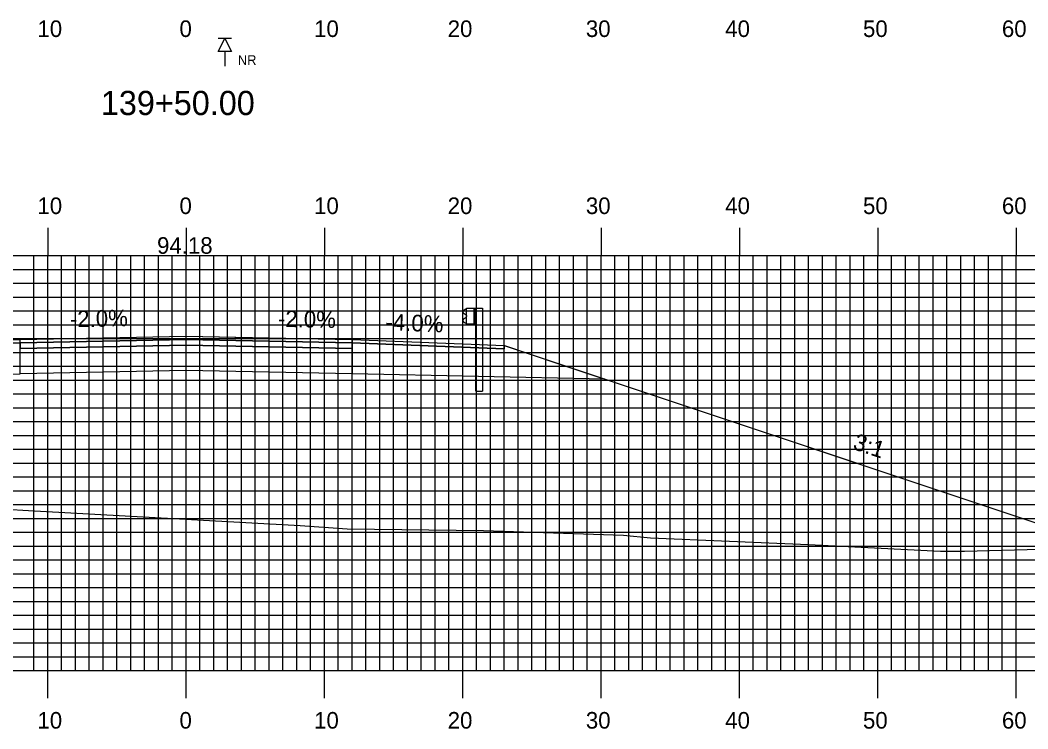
# Model space of a CAD drawing. Extents: x 1775957 to 1776301, y 442591 to 442811.
# Drawn here: x 1776111.2 to 1776184.1, y 442649.4 to 442700.7 of the extents above; entities that cross this region are included whole.
import ezdxf

# ---------------------------------------------------------------- set-up
doc = ezdxf.new("R2010")
doc.units = 0
for name, color, linetype in [('ANNOTATION', 7, 'Continuous'), ('BORING - NO REFUSAL', 7, 'Continuous'), ('D_Guardrail_Beam_Rt', 7, 'Continuous'), ('D_Roadway_Centerline', 7, 'Continuous'), ('D_Roadway_Centerline_Text', 7, 'Continuous'), ('D_Roadway_Edge_Shoulder', 7, 'Continuous'), ('D_Roadway_Edge_TW', 7, 'Continuous'), ('D_Roadway_Pavement', 7, 'Continuous'), ('D_Roadway_SlopeLines', 7, 'Continuous'), ('D_Roadway_SubGrade', 7, 'Continuous'), ('H_V ANNOTATION', 7, 'Continuous'), ('MAJOR', 7, 'Continuous'), ('MINOR', 7, 'Continuous'), ('S_Roadway_Centerline', 7, 'Continuous')]:
    doc.layers.add(name, color=color, linetype=linetype)

msp = doc.modelspace()

# ---------------------------------------------------------------- linework, layer by layer
at = {"layer": 'BORING - NO REFUSAL'}
for p, q in [((1776126.504, 442699.365), (1776125.545, 442699.365)), ((1776126.024, 442698.406), (1776126.024, 442697.347))]:
    msp.add_line(p, q, dxfattribs=at)
msp.add_lwpolyline([(1776126.024, 442699.365), (1776126.504, 442698.406), (1776125.545, 442698.406)], close=True, dxfattribs=at)
at = {"layer": 'D_Guardrail_Beam_Rt'}
for p, q in [((1776143.406, 442679.763), (1776143.262, 442679.663)), ((1776143.262, 442679.52), (1776143.458, 442679.384)), ((1776143.496, 442679.784), (1776143.422, 442679.77)), ((1776143.491, 442679.319), (1776143.491, 442679.249)), ((1776143.496, 442679.868), (1776144.183, 442679.868)), ((1776143.496, 442678.701), (1776143.496, 442679.868)), ((1776144.017, 442679.868), (1776144.017, 442678.701)), ((1776144.121, 442679.868), (1776144.121, 442678.701)), ((1776144.183, 442679.868), (1776144.654, 442679.868)), ((1776144.183, 442679.868), (1776144.183, 442678.701)), ((1776144.654, 442679.868), (1776144.654, 442673.868)), ((1776143.458, 442679.185), (1776143.262, 442679.049)), ((1776143.262, 442678.905), (1776143.406, 442678.805)), ((1776143.422, 442678.799), (1776143.496, 442678.784)), ((1776144.183, 442678.701), (1776143.496, 442678.701)), ((1776144.162, 442673.868), (1776144.162, 442678.701)), ((1776144.162, 442673.868), (1776144.654, 442673.868))]:
    msp.add_line(p, q, dxfattribs=at)
for centre, major_axis, start_param, end_param in [((1776143.313, 442679.591), (-0.0877, 0), 5.323254, 7.243116), ((1776143.43, 442679.729), (-0.0417, 0), 4.907132, 5.323254), ((1776143.412, 442679.319), (0.0789, 0), 0, 0.959931), ((1776143.313, 442678.977), (-0.0877, 0), 5.323254, 7.243116), ((1776143.43, 442678.839), (-0.0417, 0), 0.959931, 1.376053), ((1776143.412, 442679.249), (0.0789, 0), 5.323254, 6.283185)]:
    msp.add_ellipse(centre, major_axis=major_axis, ratio=0.995501, start_param=start_param, end_param=end_param, dxfattribs=at)
at = {"layer": 'D_Roadway_Centerline'}
msp.add_lwpolyline([(1776071.053, 442667.44), (1776086.85, 442672.706), (1776092.948, 442674.738), (1776100.224, 442677.164), (1776100.313, 442677.168), (1776103.223, 442677.284), (1776103.224, 442677.284), (1776103.228, 442677.284), (1776111.225, 442677.604), (1776123.222, 442677.844), (1776123.224, 442677.844), (1776129.103, 442677.727), (1776135.223, 442677.604), (1776135.225, 442677.604), (1776135.226, 442677.604), (1776143.225, 442677.284), (1776146.225, 442677.164), (1776146.228, 442677.163), (1776150.249, 442675.822), (1776153.502, 442674.738), (1776153.513, 442674.734), (1776190.006, 442662.57)], dxfattribs=at)
at = {"layer": 'D_Roadway_Edge_Shoulder'}
for points in [[(1776111.225, 442677.604), (1776103.224, 442677.284), (1776103.224, 442677.284), (1776100.224, 442677.164), (1776100.224, 442676.914), (1776111.225, 442677.354)], [(1776135.225, 442677.604), (1776143.225, 442677.284), (1776143.225, 442677.284), (1776146.225, 442677.164), (1776146.225, 442676.914), (1776135.225, 442677.354)]]:
    msp.add_lwpolyline(points, close=True, dxfattribs=at)
at = {"layer": 'D_Roadway_Edge_TW'}
msp.add_lwpolyline([(1776111.225, 442677.354), (1776111.225, 442677.604), (1776123.224, 442677.844), (1776135.225, 442677.604), (1776135.225, 442677.354), (1776123.224, 442677.594)], close=True, dxfattribs=at)
at = {"layer": 'D_Roadway_Pavement'}
msp.add_lwpolyline([(1776111.225, 442676.937), (1776111.225, 442677.354), (1776123.224, 442677.594), (1776135.225, 442677.354), (1776135.225, 442676.937), (1776123.224, 442677.177)], close=True, dxfattribs=at)
for points in [[(1776111.225, 442677.354), (1776111.225, 442676.937)], [(1776135.225, 442677.354), (1776135.225, 442676.937)]]:
    msp.add_lwpolyline(points, dxfattribs=at)
at = {"layer": 'D_Roadway_SlopeLines'}
msp.add_lwpolyline([(1776146.225, 442677.164), (1776190.006, 442662.57)], dxfattribs=at)
at = {"layer": 'D_Roadway_SubGrade'}
for points in [[(1776111.225, 442676.937), (1776111.225, 442677.354), (1776100.224, 442676.914), (1776100.224, 442677.164), (1776092.948, 442674.738), (1776111.225, 442675.104)], [(1776111.225, 442675.104), (1776111.225, 442677.354), (1776111.225, 442676.937), (1776123.224, 442677.177), (1776135.225, 442676.937), (1776135.225, 442677.354), (1776135.225, 442675.104), (1776123.224, 442675.344)], [(1776135.225, 442676.937), (1776135.225, 442677.354), (1776146.225, 442676.914), (1776146.225, 442677.164), (1776153.501, 442674.738), (1776135.225, 442675.104)]]:
    msp.add_lwpolyline(points, close=True, dxfattribs=at)
at = {"layer": 'MAJOR'}
for p, q in [((1776113.224, 442685.669), (1776113.224, 442683.665)), ((1776123.224, 442685.669), (1776123.224, 442683.665)), ((1776133.224, 442685.669), (1776133.224, 442683.665)), ((1776143.224, 442685.669), (1776143.224, 442683.665)), ((1776153.224, 442685.669), (1776153.224, 442683.665)), ((1776163.224, 442685.669), (1776163.224, 442683.665)), ((1776173.224, 442685.669), (1776173.224, 442683.665)), ((1776183.224, 442685.669), (1776183.224, 442683.665)), ((1775983.224, 442683.665), (1776263.224, 442683.665)), ((1775983.224, 442683.665), (1776263.224, 442683.665)), ((1776113.224, 442653.665), (1776113.224, 442683.665)), ((1776123.224, 442653.665), (1776123.224, 442683.665)), ((1776133.224, 442653.665), (1776133.224, 442683.665)), ((1776143.224, 442653.665), (1776143.224, 442683.665)), ((1776153.224, 442653.665), (1776153.224, 442683.665)), ((1776163.224, 442653.665), (1776163.224, 442683.665)), ((1776173.224, 442653.665), (1776173.224, 442683.665)), ((1776183.224, 442653.665), (1776183.224, 442683.665)), ((1775983.224, 442678.665), (1776263.224, 442678.665)), ((1775983.224, 442673.665), (1776263.224, 442673.665)), ((1775983.224, 442668.665), (1776263.224, 442668.665)), ((1775983.224, 442663.665), (1776263.224, 442663.665)), ((1775983.224, 442658.665), (1776263.224, 442658.665)), ((1775983.224, 442653.665), (1776263.224, 442653.665)), ((1775983.224, 442653.665), (1776263.224, 442653.665)), ((1776113.224, 442651.661), (1776113.224, 442653.665)), ((1776123.224, 442651.661), (1776123.224, 442653.665)), ((1776133.224, 442651.661), (1776133.224, 442653.665)), ((1776143.224, 442651.661), (1776143.224, 442653.665)), ((1776153.224, 442651.661), (1776153.224, 442653.665)), ((1776163.224, 442651.661), (1776163.224, 442653.665)), ((1776173.224, 442651.661), (1776173.224, 442653.665)), ((1776183.224, 442651.661), (1776183.224, 442653.665))]:
    msp.add_line(p, q, dxfattribs=at)
at = {"layer": 'MINOR'}
for p, q in [((1776112.224, 442653.665), (1776112.224, 442683.665)), ((1776114.224, 442653.665), (1776114.224, 442683.665)), ((1776115.224, 442653.665), (1776115.224, 442683.665)), ((1776116.224, 442653.665), (1776116.224, 442683.665)), ((1776117.224, 442653.665), (1776117.224, 442683.665)), ((1776118.224, 442653.665), (1776118.224, 442683.665)), ((1776119.224, 442653.665), (1776119.224, 442683.665)), ((1776120.224, 442653.665), (1776120.224, 442683.665)), ((1776121.224, 442653.665), (1776121.224, 442683.665)), ((1776122.224, 442653.665), (1776122.224, 442683.665)), ((1776124.224, 442653.665), (1776124.224, 442683.665)), ((1776125.224, 442653.665), (1776125.224, 442683.665)), ((1776126.224, 442653.665), (1776126.224, 442683.665)), ((1776127.224, 442653.665), (1776127.224, 442683.665)), ((1776128.224, 442653.665), (1776128.224, 442683.665)), ((1776129.224, 442653.665), (1776129.224, 442683.665)), ((1776130.224, 442653.665), (1776130.224, 442683.665)), ((1776131.224, 442653.665), (1776131.224, 442683.665)), ((1776132.224, 442653.665), (1776132.224, 442683.665)), ((1776134.224, 442653.665), (1776134.224, 442683.665)), ((1776135.224, 442653.665), (1776135.224, 442683.665)), ((1776136.224, 442653.665), (1776136.224, 442683.665)), ((1776137.224, 442653.665), (1776137.224, 442683.665)), ((1776138.224, 442653.665), (1776138.224, 442683.665)), ((1776139.224, 442653.665), (1776139.224, 442683.665)), ((1776140.224, 442653.665), (1776140.224, 442683.665)), ((1776141.224, 442653.665), (1776141.224, 442683.665)), ((1776142.224, 442653.665), (1776142.224, 442683.665)), ((1776144.224, 442653.665), (1776144.224, 442683.665)), ((1776145.224, 442653.665), (1776145.224, 442683.665)), ((1776146.224, 442653.665), (1776146.224, 442683.665)), ((1776147.224, 442653.665), (1776147.224, 442683.665)), ((1776148.224, 442653.665), (1776148.224, 442683.665)), ((1776149.224, 442653.665), (1776149.224, 442683.665)), ((1776150.224, 442653.665), (1776150.224, 442683.665)), ((1776151.224, 442653.665), (1776151.224, 442683.665)), ((1776152.224, 442653.665), (1776152.224, 442683.665)), ((1776154.224, 442653.665), (1776154.224, 442683.665)), ((1776155.224, 442653.665), (1776155.224, 442683.665)), ((1776156.224, 442653.665), (1776156.224, 442683.665)), ((1776157.224, 442653.665), (1776157.224, 442683.665)), ((1776158.224, 442653.665), (1776158.224, 442683.665)), ((1776159.224, 442653.665), (1776159.224, 442683.665)), ((1776160.224, 442653.665), (1776160.224, 442683.665)), ((1776161.224, 442653.665), (1776161.224, 442683.665)), ((1776162.224, 442653.665), (1776162.224, 442683.665)), ((1776164.224, 442653.665), (1776164.224, 442683.665)), ((1776165.224, 442653.665), (1776165.224, 442683.665)), ((1776166.224, 442653.665), (1776166.224, 442683.665)), ((1776167.224, 442653.665), (1776167.224, 442683.665)), ((1776168.224, 442653.665), (1776168.224, 442683.665)), ((1776169.224, 442653.665), (1776169.224, 442683.665)), ((1776170.224, 442653.665), (1776170.224, 442683.665)), ((1776171.224, 442653.665), (1776171.224, 442683.665)), ((1776172.224, 442653.665), (1776172.224, 442683.665)), ((1776174.224, 442653.665), (1776174.224, 442683.665)), ((1776175.224, 442653.665), (1776175.224, 442683.665)), ((1776176.224, 442653.665), (1776176.224, 442683.665)), ((1776177.224, 442653.665), (1776177.224, 442683.665)), ((1776178.224, 442653.665), (1776178.224, 442683.665)), ((1776179.224, 442653.665), (1776179.224, 442683.665)), ((1776180.224, 442653.665), (1776180.224, 442683.665)), ((1776181.224, 442653.665), (1776181.224, 442683.665)), ((1776182.224, 442653.665), (1776182.224, 442683.665)), ((1775983.224, 442682.665), (1776263.224, 442682.665)), ((1775983.224, 442681.665), (1776263.224, 442681.665)), ((1775983.224, 442680.665), (1776263.224, 442680.665)), ((1775983.224, 442679.665), (1776263.224, 442679.665)), ((1775983.224, 442677.665), (1776263.224, 442677.665)), ((1775983.224, 442676.665), (1776263.224, 442676.665)), ((1775983.224, 442675.665), (1776263.224, 442675.665)), ((1775983.224, 442674.665), (1776263.224, 442674.665)), ((1775983.224, 442672.665), (1776263.224, 442672.665)), ((1775983.224, 442671.665), (1776263.224, 442671.665)), ((1775983.224, 442670.665), (1776263.224, 442670.665)), ((1775983.224, 442669.665), (1776263.224, 442669.665)), ((1775983.224, 442667.665), (1776263.224, 442667.665)), ((1775983.224, 442666.665), (1776263.224, 442666.665)), ((1775983.224, 442665.665), (1776263.224, 442665.665)), ((1775983.224, 442664.665), (1776263.224, 442664.665)), ((1775983.224, 442662.665), (1776263.224, 442662.665)), ((1775983.224, 442661.665), (1776263.224, 442661.665)), ((1775983.224, 442660.665), (1776263.224, 442660.665)), ((1775983.224, 442659.665), (1776263.224, 442659.665)), ((1775983.224, 442657.665), (1776263.224, 442657.665)), ((1775983.224, 442656.665), (1776263.224, 442656.665)), ((1775983.224, 442655.665), (1776263.224, 442655.665)), ((1775983.224, 442654.665), (1776263.224, 442654.665))]:
    msp.add_line(p, q, dxfattribs=at)
at = {"layer": 'S_Roadway_Centerline'}
msp.add_lwpolyline([(1776052.813, 442668.565), (1776060.782, 442668.128), (1776066.578, 442667.743), (1776084.479, 442666.531), (1776086.64, 442666.422), (1776088.774, 442666.328), (1776108.571, 442665.416), (1776111.819, 442665.238), (1776131.456, 442664.142), (1776134.859, 442663.901), (1776144.732, 442663.79), (1776154.832, 442663.446), (1776156.793, 442663.259), (1776168.226, 442662.786), (1776177.768, 442662.295), (1776179.483, 442662.287), (1776191.245, 442662.603)], dxfattribs=at)

# ---------------------------------------------------------------- texts
at = {"layer": 'ANNOTATION'}
for s, rotation, p in [('-2.0%', 1.14584, (1776114.83, 442678.477)), ('-2.0%', 358.85429, (1776129.849, 442678.512)), ('-4.0%', 357.70939, (1776137.613, 442678.274)), ('3:1', 341.56528, (1776171.363, 442669.693))]:
    msp.add_text(s, height=1.2, rotation=rotation, dxfattribs=at).set_placement(p)
at = {"layer": 'BORING - NO REFUSAL'}
msp.add_text('NR', height=0.6998, dxfattribs=at).set_placement((1776126.957, 442697.45))
at = {"layer": 'D_Roadway_Centerline'}
for s, p in [('C', (1776123.219, 442677.844)), ('L', (1776123.224, 442677.837))]:
    msp.add_text(s, height=0.0146, dxfattribs=at).set_placement(p)
at = {"layer": 'D_Roadway_Centerline_Text'}
msp.add_text('94.18', height=1.2, dxfattribs=at).set_placement((1776121.122, 442683.793))
at = {"layer": 'H_V ANNOTATION'}
for s, height, p in [('10', 1.2, (1776112.475, 442699.465)), ('0', 1.2, (1776122.743, 442699.465)), ('10', 1.2, (1776132.475, 442699.465)), ('20', 1.2, (1776142.132, 442699.465)), ('30', 1.2, (1776152.122, 442699.465)), ('40', 1.2, (1776162.197, 442699.465)), ('50', 1.2, (1776172.154, 442699.465)), ('60', 1.2, (1776182.197, 442699.465)), ('139+50.00', 1.75, (1776117.06, 442693.821)), ('10', 1.2, (1776112.475, 442686.665)), ('0', 1.2, (1776122.743, 442686.665)), ('10', 1.2, (1776132.475, 442686.665)), ('20', 1.2, (1776142.132, 442686.665)), ('30', 1.2, (1776152.122, 442686.665)), ('40', 1.2, (1776162.197, 442686.665)), ('50', 1.2, (1776172.154, 442686.665)), ('60', 1.2, (1776182.197, 442686.665)), ('10', 1.2, (1776112.475, 442649.465)), ('0', 1.2, (1776122.743, 442649.465)), ('10', 1.2, (1776132.475, 442649.465)), ('20', 1.2, (1776142.132, 442649.465)), ('30', 1.2, (1776152.122, 442649.465)), ('40', 1.2, (1776162.197, 442649.465)), ('50', 1.2, (1776172.154, 442649.465)), ('60', 1.2, (1776182.197, 442649.465))]:
    msp.add_text(s, height=height, dxfattribs=at).set_placement(p)

doc.saveas('drawing.dxf')
